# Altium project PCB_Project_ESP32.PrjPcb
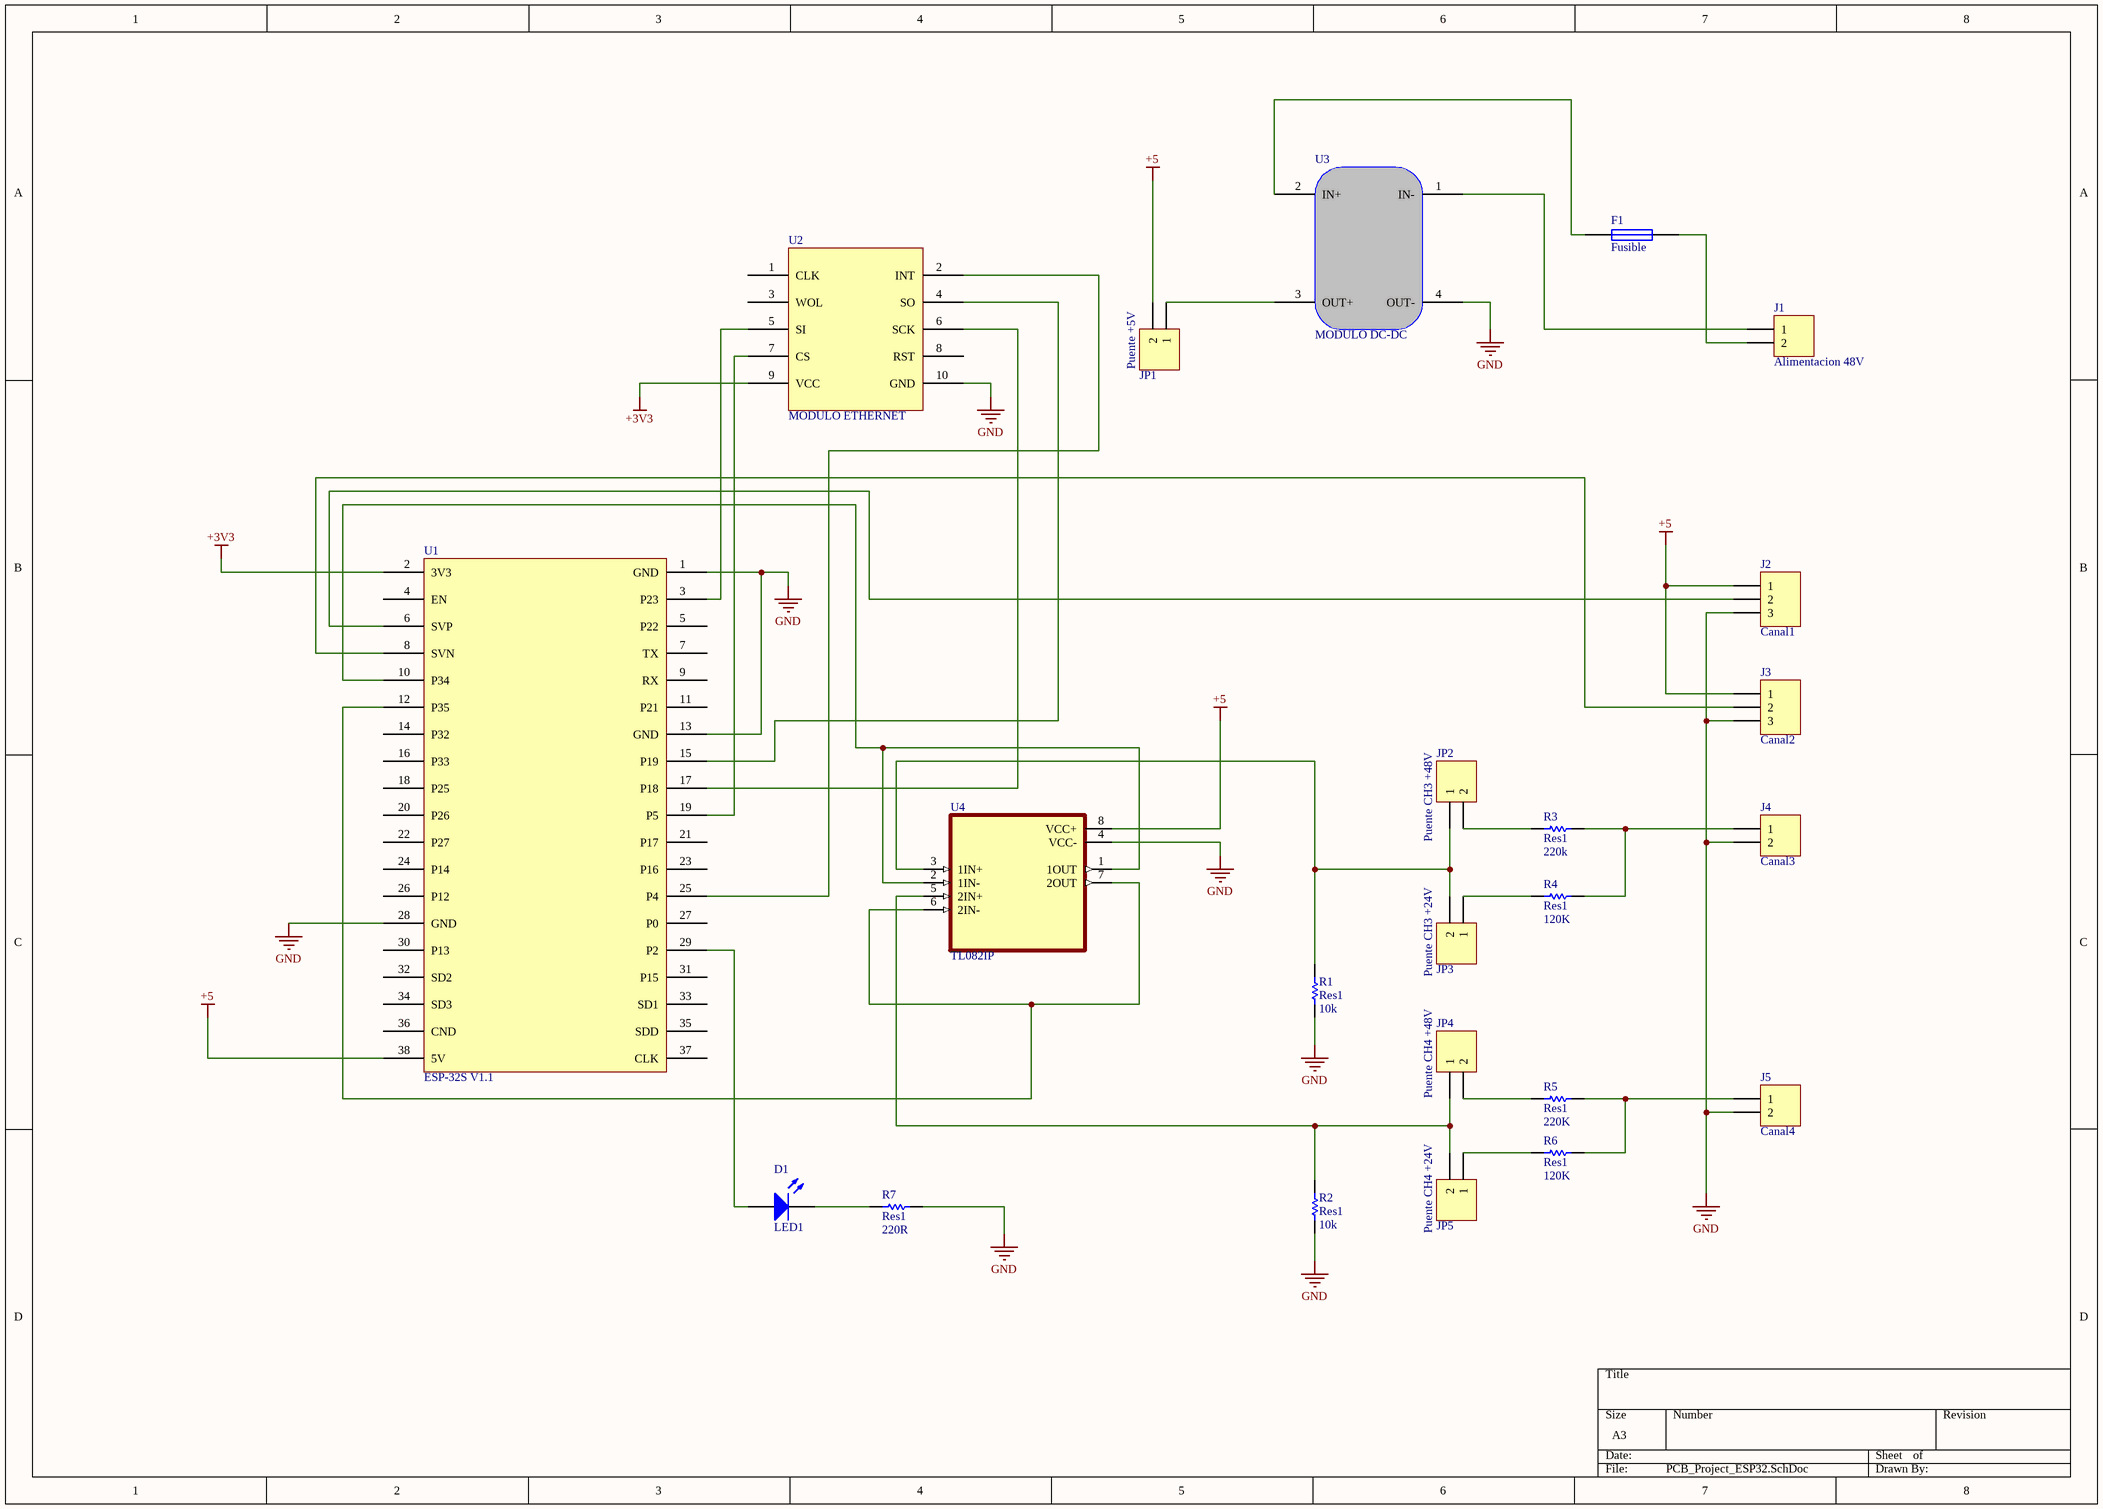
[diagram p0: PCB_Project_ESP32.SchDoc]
1 sheet, 23 parts. Net scope: global (net labels, ports and power ports of the same name join across sheets).
Board file: PCB_Project_ESP32.PcbDoc

## Sheet PCB_Project_ESP32.SchDoc
size A3

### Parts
D1  LED1  [HEADER 2X1]
F1  Fusible  [HEADER 2X1]
J1  Alimentacion 48V  [BORNERA 2 (5MM)]
J2  Canal1  [Bornera 3 (5mm)]
J3  Canal2  [Bornera 3 (5mm)]
J4  Canal3  [BORNERA 2 (5MM)]
J5  Canal4  [BORNERA 2 (5MM)]
JP1  Puente +5V  [HEADER 2X1]
JP2  Puente CH3 +48V  [HEADER 2X1]
JP3  Puente CH3 +24V  [HEADER 2X1]
JP4  Puente CH4 +48V  [HEADER 2X1]
JP5  Puente CH4 +24V  [HEADER 2X1]
R1  Res1  value 10k  [AXIAL-0.3]
R2  Res1  value 10k  [AXIAL-0.3]
R3  Res1  value 220k  [AXIAL-0.3]
R4  Res1  value 120K  [AXIAL-0.3]
R5  Res1  value 220K  [AXIAL-0.3]
R6  Res1  value 120K  [AXIAL-0.3]
R7  Res1  value 220R  [AXIAL-0.3]
U1  ESP-32S V1.1  [ESP-32S V1.1]
U2  MODULO ETHERNET  [MODULO ETHERNET]
U3  MODULO DC-DC  [MODULO DC-DC]
U4  TL082IP  [DIP794W45P254L959H508Q8]

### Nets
+3V3: U1.2(3V3) U2.9(VCC)
+5: J2.1 J3.1 JP1.2 U1.38(5V) U4.8(VCC+)
GND: J2.3 J3.3 J4.2 J5.2 R1.1 R2.1 R7.2 U1.1(GND) U1.13(GND) U1.28(GND) U2.10(GND) U3.4(OUT-) U4.4(VCC-)
NetD1_1: D1.1(A) U1.29(P2)
NetD1_2: D1.2(K) R7.1
NetF1_1: F1.1 U3.2(IN+)
NetF1_2: F1.2 J1.2
NetJ1_1: J1.1 U3.1(IN-)
NetJ2_2: J2.2 U1.6(SVP)
NetJ3_2: J3.2 U1.8(SVN)
NetJ4_1: J4.1 R3.2 R4.2
NetJ5_1: J5.1 R5.2 R6.2
NetJP1_1: JP1.1 U3.3(OUT+)
NetJP2_1: JP2.1 JP3.2 R1.2 U4.3(1IN+)
NetJP2_2: JP2.2 R3.1
NetJP3_1: JP3.1 R4.1
NetJP4_1: JP4.1 JP5.2 R2.2 U4.5(2IN+)
NetJP4_2: JP4.2 R5.1
NetJP5_1: JP5.1 R6.1
NetU1_3: U1.3(P23) U2.5(SI)
NetU1_10: U1.10(P34) U4.1(1OUT) U4.2(1IN-)
NetU1_12: U1.12(P35) U4.6(2IN-) U4.7(2OUT)
NetU1_15: U1.15(P19) U2.4(SO)
NetU1_17: U1.17(P18) U2.6(SCK)
NetU1_19: U1.19(P5) U2.7(CS)
NetU1_25: U1.25(P4) U2.2(INT)

Not connected (* = marked no-connect by the designer): U1 4(EN) 5(P22) 7(TX) 9(RX) 11(P21) 14(P32) 16(P33) 18(P25) 20(P26) 21(P17) 22(P27) 23(P16) 24(P14) 26(P12) 27(P0) 30(P13) 31(P15) 32(SD2) 33(SD1) 34(SD3) 35(SDD) 36(CND) 37(CLK); U2 1(CLK) 3(WOL) 8(RST)

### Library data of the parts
D1 = LED1: Typical RED GaAs LED
F1 = Fuse 1: Fuse
J1 J4 J5 JP1-JP5 = Header 2: Header, 2-Pin
J2 J3 = Header 3: Header, 3-Pin
R1-R7 = Res1: Resistor
U1 = ESP-32S V1.1: ESP-32S V1.1 NODEMCU
U2 = MODULO ETHERNET: MOD ETHETNET ARDUINO HR911105A
U3 = MODULO DC-DC: REG STEP DOWN LM2576HV DC-DC 5-60V
U4 = TL082IP: Dual, 30-V, 3-MHz, 13-V/Âµs slew rate, In to V+, JFET-input op amp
